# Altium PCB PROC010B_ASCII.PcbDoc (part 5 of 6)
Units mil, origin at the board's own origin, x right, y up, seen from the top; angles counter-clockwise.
Board outline 3180 x 2565 mil, 6 copper layers (TOP, L2, L3, L4, L5, BOTTOM), stack 55.54 mil thick; 362 components, 264 nets, 1248 pads, 1144 vias.
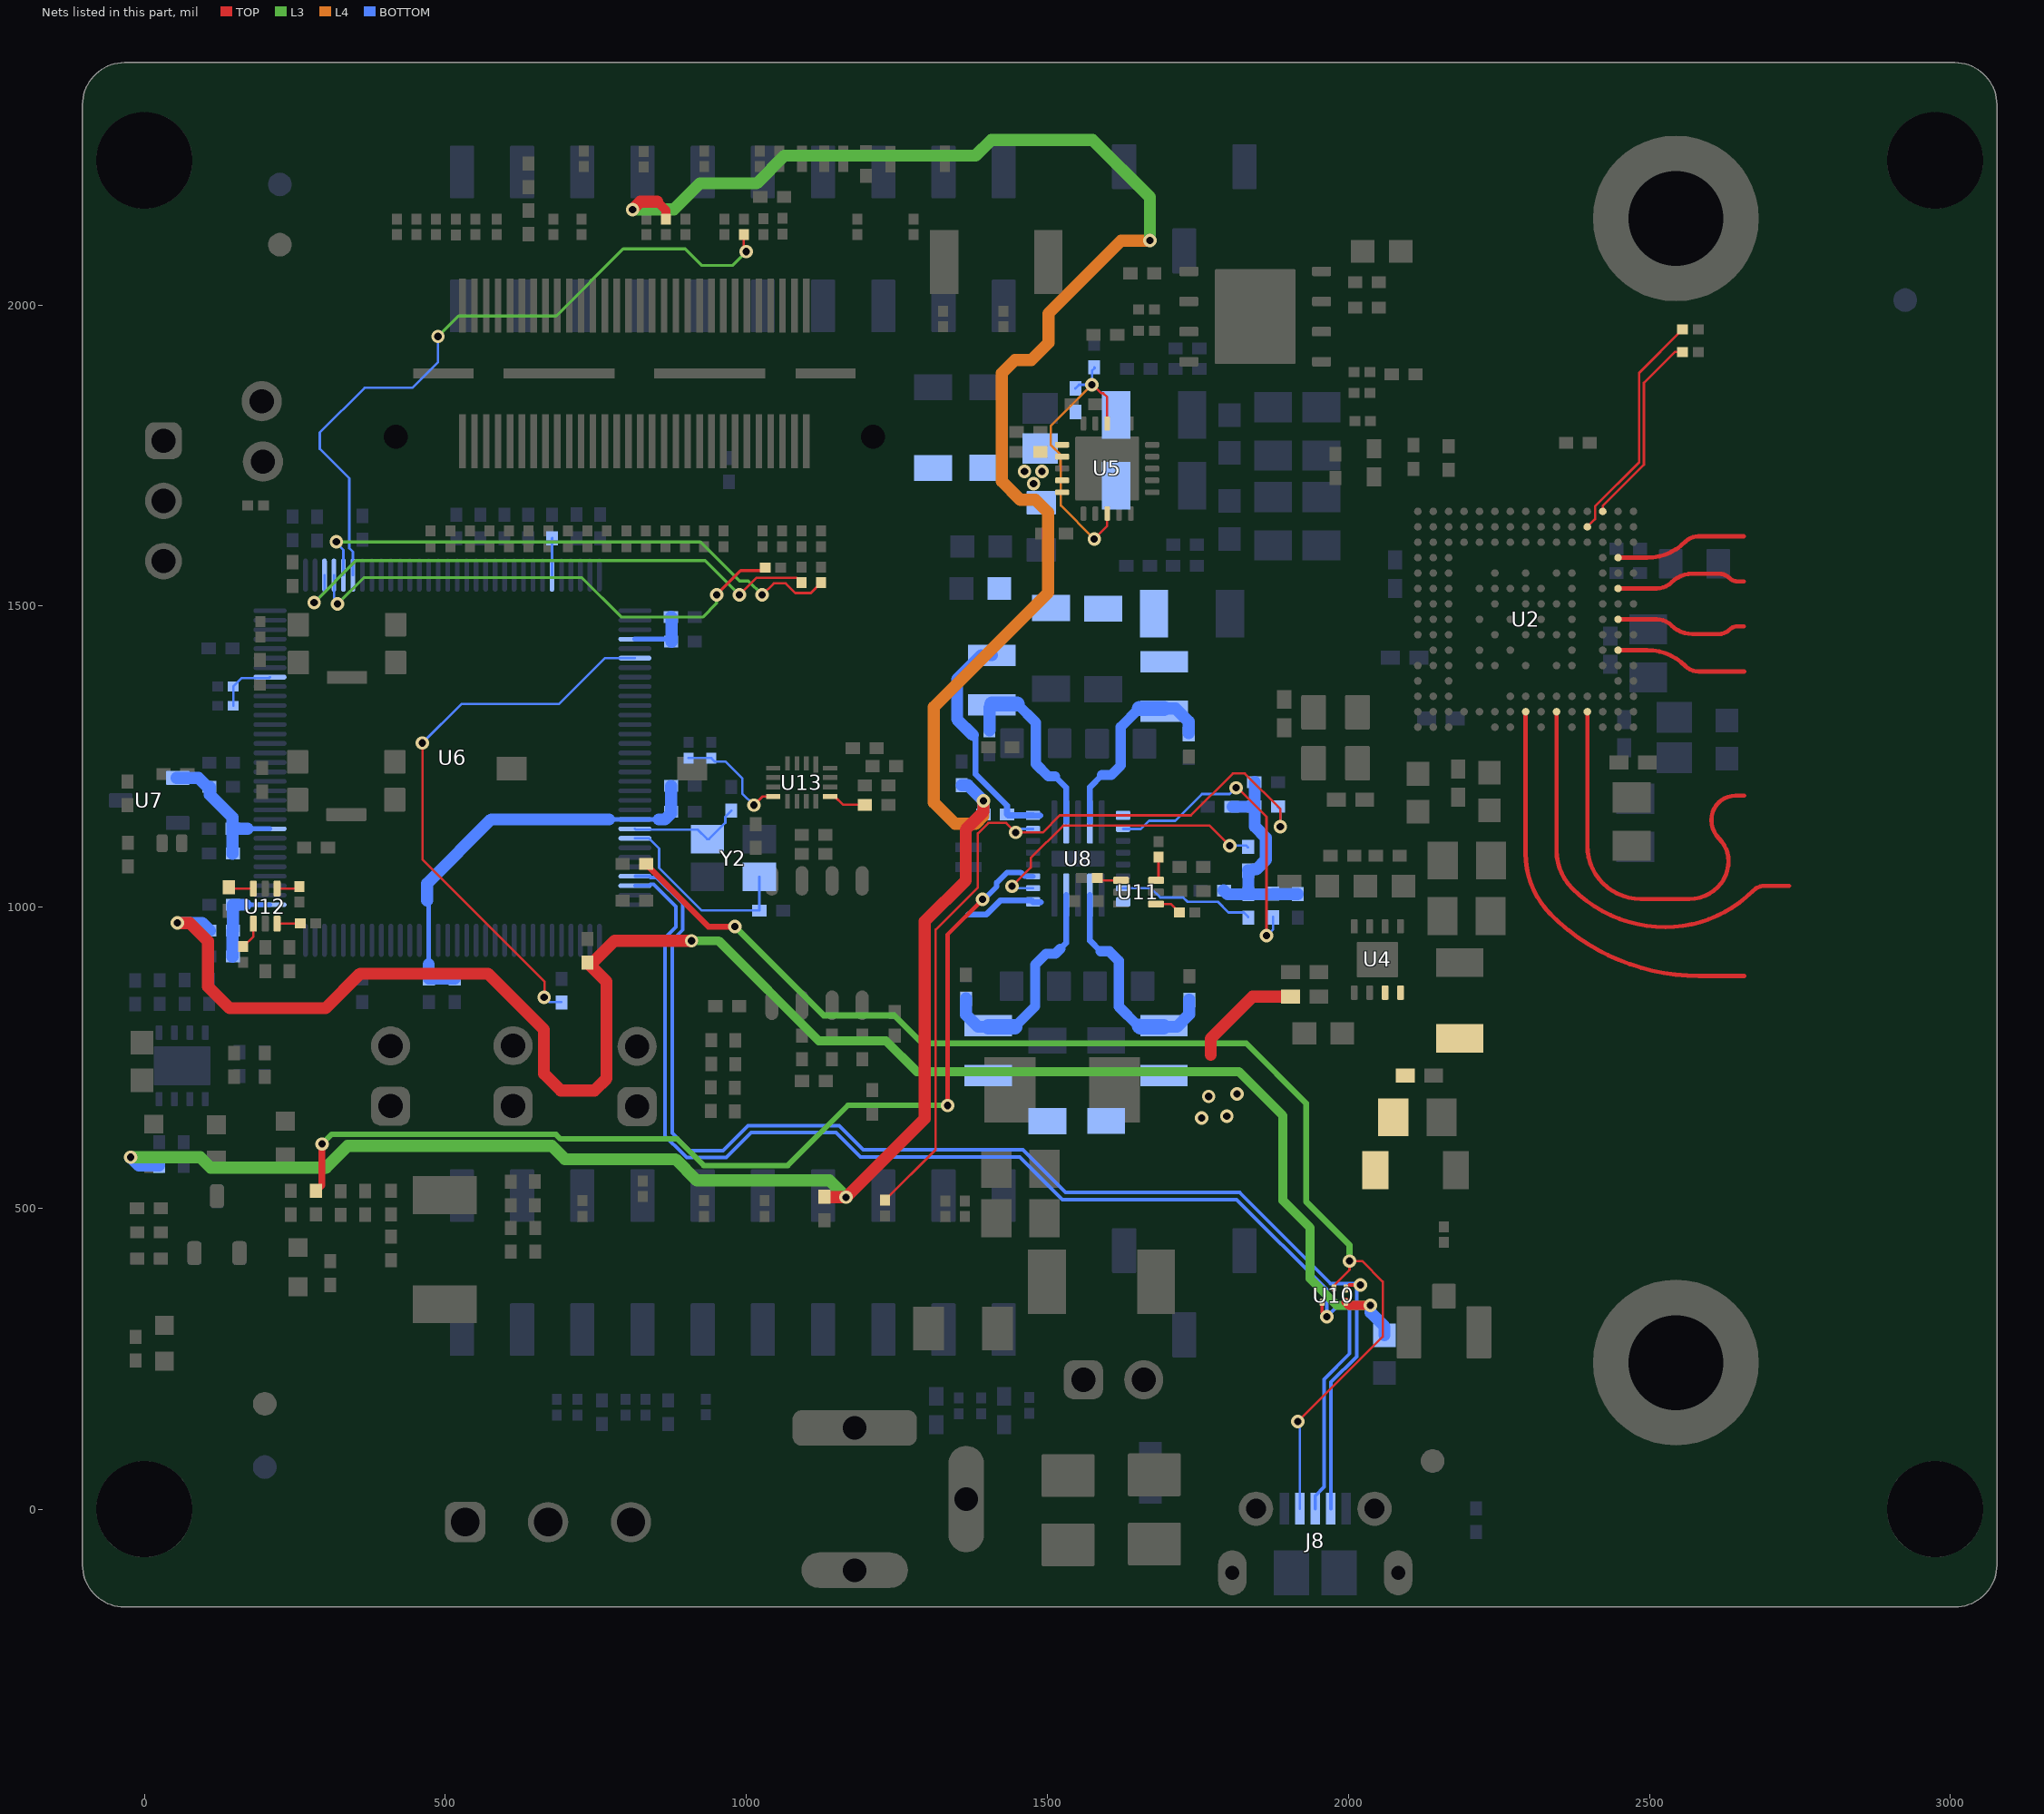
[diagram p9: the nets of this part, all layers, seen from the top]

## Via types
v1: diameter 22.4, hole 12.2, TOP to BOTTOM, tented both sides, 621 vias
v2: diameter 15.74, hole 5.9, TOP to L2, tented top, 508 vias
v3: diameter 19.68, hole 7.87, TOP to BOTTOM, tented top, 7 vias
v4: diameter 19.68, hole 7.87, TOP to BOTTOM, 4 vias
v5: diameter 19.68, hole 7.87, TOP to BOTTOM, tented both sides, 3 vias
v6: diameter 19.68, hole 7.87, TOP to BOTTOM, tented bottom, 1 vias

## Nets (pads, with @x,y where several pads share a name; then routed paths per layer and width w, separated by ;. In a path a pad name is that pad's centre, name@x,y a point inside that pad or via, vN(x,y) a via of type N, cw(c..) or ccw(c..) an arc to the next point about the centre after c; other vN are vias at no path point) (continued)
NetR180_2: R180.2 U11.1 | length 41.2
  TOP w4: R180.2@1582.77,1048.33 1586.66,1044.44 U11.1@1622.33,1044.44
NetR181_1: R181.1 U11.4 | length 44.4
  TOP w4: U11.4@1680.59,1005.07 1705.34,1005.06 R181.1@1719.23,991.17
NetR182_1: R182.1 U11.6 | length 40
  TOP w4: U11.6@1680.59,1044.44 1684.67,1048.52 R182.1@1684.67,1082.79
NetR184_1: R184.1 U12.3 | length 41.4
  TOP w4: R184.1@140.38,1032.25 141.96,1030.67 U12.3@181.13,1030.67
NetR185_2: R185.2 U12.1 | length 38.8
  TOP w4: U12.1@220.5,1030.67 254.29,1030.67 R185.2@257.83,1034.21
NetR186_1: R186.1 U12.6 | length 38.7
  TOP w4: U12.6@220.5,972.4 257.87,972.41 R186.1@258.79,973.33
NetR188_2: R188.2 U12.4 | length 45.4
  TOP w4: R188.2@163.83,934.21 181.12,951.5 U12.4@181.13,972.4
NetR194_2: R194.2 U6.59 | length 61.9
  BOTTOM w4: U6.59@677.14,1551.19 677.14,1612.57 R194.2@677.52,1612.95
NetR195_1: R195.1 U13.13 | length 63.2
  TOP w4: U13.13@1139.1,1183.59 1146.9,1183.59 1160.68,1169.81 R195.1@1196.58,1169.81
NetR197_2: R197.2 U2.P4 | length 393.5
  TOP w4: U2.P4@2396.91,1631.44 2409.75,1644.28 2409.75,1665.25 2483,1738.5 2483,1887.2 2555.01,1959.21 R197.2@2555.01,1959
NetR198_2: R198.2 U2.R3 | length 327.3
  TOP w4: U2.R3@2422.5,1657.03 2422.5,1666 2491,1734.5 2491,1870.64 2542.36,1922 R198.2@2555.01,1922
PGOOD: R27.1 R107.2 R138.2 R141.2 R159.1 | length 4589.2
  TOP w15: 852.15,2171.36 866.61,2156.9 R27.1@866.61,2142.71
  TOP w20: v1(811,2158.5) 823.86,2171.36 852.15,2171.36 ; R107.2@1129.75,518.18 v1(1165.78,518.18) 1296.38,648.78 1296.38,976.2 1364.54,1044.36 1364.54,1129.13 1393.72,1158.31 v1(1393.72,1176.67)
  L3 w20: v1(-23,584.5) 93.04,584.5 110.2,567.34 301.89,567.34 337.84,603.3 676.71,603.3 698.74,581.28 882.26,581.28 917.54,546 1137.96,546 v1(1165.78,518.18) ; v1(811,2158.5) 879.46,2158.5 922.83,2201.86 1017.13,2201.86 1063.27,2248 1381,2248 1407,2274 1575.14,2274 1670.34,2178.8 v1(1670.34,2106.77)
  L4 w20: v1(1393.72,1176.67) 1393.72,1150.96 1381.05,1138.3 1346.64,1138.3 1311.35,1173.59 1311.35,1332.35 1501.24,1522.24 1501.24,1655.5 1480.29,1676.45 1454.85,1676.45 1424.36,1706.93 1424.36,1886.63 1446.28,1908.55 1473.25,1908.55 1501.76,1937.06 1501.76,1985.85 1622.68,2106.77 v1(1670.34,2106.77)
  BOTTOM w20: v1(-23,584.5) -9.31,570.81 R159.1@24.43,570.81 ; R138.2@1357.78,1202.28 1368.11,1202.28 v1(1393.72,1176.67) R141.2@1393.72,1154.01
PMIC_1V0: C30.2 C31.2 C32.2 C40.2 C81.2 L4.2 L5.1 L8.1 R46.1 R120.2 U5.1 U5.2 U5.4 U5.5 U8.1 | length 130.9
  BOTTOM w10: 1368.72,987.88 1398.93,987.88 1422.37,1011.32 1473.53,1011.32 U8.1@1476.2,1008.65 ; U8.1@1476.2,1007.88 1488.82,1007.88
  other v1: 1477.07,1703.31 1461.98,1723.32 1491.25,1723.21
PMIC_1V2: C54.2 L1.2 L9.1 U8.14
PMIC_1V8: C21.1 C23.1 C25.1 C82.2 L3.2 L7.1 R84.2 U4.7 U4.8 U8.21 | length 188.3
  TOP w20: 1771.28,754.5 1771.28,781.5 1841,851.22 R84.2@1903.73,851.22
  other v1: 1756,649.5 1798,652.5 1768,685.5 1815,689.5
PMIC_CLK: R97.2 U8.3 | length 1666.1
  TOP w7.08: v1(1334.3,670.49) 1334.3,954.63 v1(1392.53,1012.86)
  TOP w11: R97.2@285,528.05 295,538.05 v1(295,606.5)
  L3 w9: v1(295,606.5) 310.78,622.28 683.9,622.28 691.42,614.75 885.25,614.75 929.05,570.95 1068.95,570.95 1168.49,670.49 v1(1334.3,670.49)
  BOTTOM w9: v1(1392.53,1012.86) 1394.86,1012.86 1416,1034 1416,1040.48 1433.11,1057.59 1455.85,1057.59 1462.47,1050.97 U8.3@1476.2,1050.97
PMIC_EN1: R102.2 R142.1 U8.7 | length 1350.2
  TOP w4: R102.2@1230.25,513.27 1314.37,597.39 1314.37,962.49 1384.59,1032.71 1384.59,1122.31 1401.99,1139.71 1431.79,1139.71 v1(1447.5,1124) 1492.41,1124 1520.75,1152.33 1738.33,1152.33 1808,1222 1828,1222 1887,1163 v1(1887,1133.5)
  BOTTOM w4: v1(1447.5,1124) 1453.21,1129.71 U8.7@1476.2,1129.71 ; R142.1@1882.25,1167.04 1887,1162.29 v1(1887,1133.5)
PMIC_EN2: R148.1 U8.15 | length 520.5
  TOP w4: v1(1813.65,1198) 1816,1198 1864,1150 v1(1864,952.5)
  BOTTOM w4: U8.15@1625.81,1129.71 1655.21,1129.71 1668.82,1143.32 1712.32,1143.32 1756.81,1187.81 1802.78,1187.81 1813.65,1198.69 v1(1813.65,1198) ; v1(1864,952.5) 1875,963.5 R148.1@1875,983.6
PMIC_EN3: R145.1 U8.2 | length 494.2
  TOP w4: v1(1441.5,1034.5) 1472.48,1065.48 1472.48,1081.57 1526.25,1135.33 1769.67,1135.33 v1(1803,1102)
  BOTTOM w4: v1(1441.5,1034.5) 1444.71,1031.29 U8.2@1476.2,1031.28 ; v1(1803,1102) 1830.49,1102 R145.1@1833.44,1099.05
PMIC_NRST: R150.2 U8.20 | length 227.8
  BOTTOM w4: U8.20@1625.81,1031.28 1672.21,1031.29 1687.5,1016 1725.5,1016 1732.5,1009 1782.99,1009 1800.99,991 1825.99,991 R150.2@1833.74,983.25
PMICOUT_3V3: C55.2 L2.2 R133.1 R141.1 U8.8 | length 388.9
  BOTTOM w10: 1376.47,1285.53 1380.65,1281.35 1380.65,1220.85 1433.09,1168.41 R141.1@1433.09,1154.01 1434.74,1152.35 U8.8@1476.2,1152.35 ; U8.8@1476.2,1152.15 1488.2,1152.15
  BOTTOM w20: 1376.47,1285.53 1350,1312 1350,1378.33 1389.91,1418.24 L2.2@1407.85,1418.24
PMICVIO_3V3: R139.2 R142.2 R143.2 R145.2 R147.2 R148.2 R149.1 R150.1 | length 376.5
  BOTTOM w20: R147.2@1792.9,1027.5 1799.35,1021.05 R150.1@1833.74,1021.05 ; R143.2@1807.91,1166.5 R142.2@1844.45,1167.04 ; R139.2@1844.45,1207.54 R142.2@1844.45,1167.04 ; R149.1@1916.14,1021.05 1915.79,1021.4 1875,1021.4 1874.65,1021.05 R150.1@1833.74,1021.05 ; R150.1@1833.74,1021.05 1833.74,1060.95 1833.44,1061.25 1840.75,1061.25 1842,1062.5 1847,1062.5 1863,1078.5 1863,1115 1844.45,1133.55 R142.2@1844.45,1167.04
RX1: U2.M2 | length 218.6
  TOP w7.08: U2.M2@2448.09,1580.26 2496.4,1580.26 ccw(c2496.4,1669.28) 2559.79,1606.78 cw(c2581.07,1585.5) 2581.07,1615.6 2657.22,1615.6
RX2: U2.K2 | length 218.8
  TOP w7.08: U2.K2@2448.09,1529.08 2512.28,1529.08 ccw(c2512.28,1563.6) 2536.69,1539.19 cw(c2571.24,1504.66) 2571.24,1553.5 2615.82,1553.5 cw(c2615.82,1528.95) 2633.18,1546.31 ccw(c2646.47,1559.58) 2646.47,1540.8 2656.92,1540.8
RX3: U2.H2 | length 218.8
  TOP w7.08: U2.H2@2448.09,1477.9 2512.28,1477.9 cw(c2512.28,1443.38) 2536.69,1467.79 ccw(c2571.24,1502.32) 2571.24,1453.48 2615.82,1453.48 ccw(c2615.82,1478.03) 2633.18,1460.67 ; 2633.19,1460.68 cw(c2646.47,1447.4) 2646.47,1466.18 2656.92,1466.18
RX4: U2.F2 | length 218.9
  TOP w7.08: U2.F2@2448.09,1426.72 2496.4,1426.72 cw(c2496.4,1337.7) 2559.79,1400.2 ccw(c2581.5,1421.91) 2581.5,1391.2 2657.4,1391.2
SPICLK1: R75.1 R76.1 U13.8 | length 193.5
  TOP w4: v1(1012.58,1169.33) 1026.83,1183.59 U13.8@1044.61,1183.59
  BOTTOM w4: R75.1@904.07,1247.48 R76.1@941.93,1247.48 947.94,1241.48 965.54,1241.48 993.15,1213.86 993.15,1188.75 v1(1012.58,1169.33)
SS_CTRL: R119.2 R120.1 U5.8 U5.18 | length 504.4
  TOP w4: v1(1574.07,1867.4) 1575.74,1867.4 1589.91,1853.24 1592.9,1853.24 1599.35,1846.8 U5.18@1599.35,1803.12 ; v1(1577.96,1611.47) 1599.35,1632.86 U5.8@1599.35,1653.52
  L4 w4: v1(1574.07,1867.4) 1505.5,1798.83 1505.5,1767.57 1521.82,1751.25 1521.82,1731.91 1522.36,1731.91 1522.36,1667.08 v1(1577.96,1611.47)
  BOTTOM w4: R120.1@1546.63,1861.48 1552.56,1867.4 v1(1574.07,1867.4) 1574.07,1890.75 1578.87,1895.55 R119.2@1577.96,1896.45
SW0: L2.1 R190.2 U8.10 | length 322.3
  BOTTOM w10: 1512.51,1217 1531.31,1198.2 U8.10@1531.32,1141.13
  BOTTOM w17: 1449.82,1337.53 1480.85,1306.5 1480.85,1237.8 1501.65,1217 1512.51,1217
  BOTTOM w20: R190.2@1403.85,1293.43 1403.85,1331.56 L2.1@1407.85,1335.56
  BOTTOM w25: L2.1@1407.85,1337.53 1449.82,1337.53
SW1: L1.1 R191.2 U8.12 | length 342.4
  BOTTOM w10: U8.12@1570.69,1141.13 1570.69,1199.24 1590.95,1219.5
  BOTTOM w17: 1590.95,1219.5 1606.05,1219.5 1621.95,1235.4 1621.95,1299.23 1652.68,1329.96
  BOTTOM w20: L1.1@1694.05,1329.96 1713.07,1329.96 1734.8,1308.23 R191.2@1734.8,1288.55
  BOTTOM w25: 1652.68,1329.96 L1.1@1694.05,1329.96
SW2: L4.1 R192.2 U8.25 | length 379.6
  BOTTOM w10: 1521.55,930.8 1531.31,940.56 U8.25@1531.32,1019.87
  BOTTOM w17: 1445.92,801.17 1479.85,835.1 1479.85,904.34 1498.01,922.5 1513.25,922.5 1521.55,930.8
  BOTTOM w20: R192.2@1364.9,848.45 1364.9,821.17 1384.9,801.17 L4.1@1401.55,801.17
  BOTTOM w25: L4.1@1401.55,801.17 1445.92,801.17
SW3: L3.1 R193.2 U8.23 | length 377.5
  BOTTOM w10: U8.23@1570.69,1019.87 1570.69,944.32 1588.51,926.5
  BOTTOM w17: 1588.51,926.5 1602.85,926.5 1618.65,910.7 1618.65,834.7 1650.84,802.51 1652.68,802.51
  BOTTOM w20: L3.1@1693.55,801.17 1714.99,801.17 1735.6,821.78 R193.2@1735.6,846.45
  BOTTOM w25: 1652.68,802.51 1654.02,801.17 L3.1@1693.55,801.17
TX1: U2.B4 | length 696.2
  TOP w7.08: U2.B4@2396.91,1324.36 2396.91,1102.05 ccw(c2485.46,1102.05) 2485.46,1013.5 2566.65,1013.5 ccw(c2566.65,1079.79) 2613.53,1032.92 ; 2613.54,1032.93 ccw(c2570.24,1076.22) 2631.47,1076.22 ccw(c2578.8,1076.22) 2616.05,1113.46 cw(c2647.37,1144.78) 2603.07,1144.78 cw(c2643.55,1144.8) 2614.93,1173.43 cw(c2642.62,1145.76) 2642.61,1184.9 2657.3,1184.9
TX2: U2.B6 | length 696.2
  TOP w7.08: U2.B6@2345.73,1324.36 2345.73,1094.33 ccw(c2435.71,1094.33) 2372.08,1030.71 ccw(c2526.5,1185.06) 2526.5,966.73 ccw(c2526.5,1172.53) 2672,1026.99 cw(c2692.07,1006.94) 2692.06,1035.3 2732.11,1035.3
TX3: U2.B8 | length 696.3
  TOP w7.08: U2.B8@2294.55,1324.36 2294.34,1324.15 2294.34,1089.06 ccw(c2437.96,1089.06) 2336.4,987.51 ccw(c2582.22,1233.3) 2582.22,885.68 2657.3,885.68
VBUS_1_DETECT: C69.2 R151.1 R153.2 U6.1 | length 147.8
  BOTTOM w8: 168.55,1003.95 U6.1@208.64,1003.95
  BOTTOM w20: R153.2@146.55,917.74 146.55,961.04 146.95,961.44 146.95,1003.56 147.34,1003.95 168.55,1003.95
VDDC_1: C62.2 C64.2 C74.2 C75.2 U6.87 U6.115 | length 701
  BOTTOM w8: 469.65,1010.85 472.42,1008.08 472.42,905.08 ; 771.82,1145.68 854.18,1145.68
  BOTTOM w20: 469.65,1010.85 469.65,1039.15 576.18,1145.68 771.82,1145.68 ; 472.42,905.08 472.42,881.71 472.68,881.45 C74.2@515.6,881.45 ; 854.18,1145.68 865,1145.68 874.96,1155.64 C64.2@874.96,1158.3 C62.2@874.96,1201.2
XDSET_1_D_N: J8.2 U6.93 U10.1 | length 2188.8
  TOP w6: U10.1@1995.68,366.33 2001.88,372.52 v1(2019.99,372.52)
  BOTTOM w6: U6.93@815.54,1051.19 838.99,1051.19 840.8,1049.38 850.87,1049.38 894.6,1005.65 894.6,962.25 876.6,944.24 876.6,624.75 905.6,595.75 905.6,595.5 961.6,595.5 1003.1,637 1153.9,637 1194.2,596.7 1459.1,596.7 1529.89,525.91 1819.18,525.91 1970.6,374.5 2019.6,374.5 2020.6,373.5 2013.6,366.5 2013.6,335.81 2013.6,253.5 1971.19,211.09 1971.19,32.06 J8.2@1971.19,0.88
XDSET_1_D_P: J8.3 U6.94 U10.4 | length 2188.5
  TOP w6: U10.4@1956.31,343.69 1956.31,327.19 v1(1964,319.5)
  BOTTOM w6: U6.94@814.94,1035.44 838.69,1035.44 841.03,1037.78 846.07,1037.78 883,1000.85 883,967.05 865,949.05 865,619.94 894,590.94 894,590.7 900.79,583.9 966.4,583.9 1007.9,625.4 1149.1,625.4 1189.4,585.1 1454.3,585.1 1525.09,514.31 1814.38,514.31 1964,364.69 v1(1964,319.5) 1984.5,340 1993,340 2002,331 2002,258.31 1959.59,215.9 1959.59,36.86 1945,22.27 J8.3@1945,0.88
XDSET_1_ID: J8.4 R152.2 U10.2 | length 2115.1
  TOP w4: v1(1916,145.5) 2057.04,286.54 2057.04,377.81 2022.74,412.11 v1(2001.89,412.11) 2001.89,397.39 1976,371.5 U10.2@1976,367.31
  TOP w10: R152.2@832.9,1071.5 936.9,967.5 v1(981,967.5)
  L3 w10: v1(981,967.5) 1128.41,820.09 1245.8,820.09 1292.12,773.77 1830.37,773.77 1929.79,674.35 1929.79,510.85 2001.89,438.76 v1(2001.89,412.11)
  BOTTOM w4: v1(1916,145.5) 1919.41,142.09 J8.4@1919.41,0.88
XDSET_1_VBUS: R151.2 R154.2 R161.2 U10.6 | length 3036.4
  TOP w15: U10.6@1995.68,343.69 2000.79,338.59 v1(2036.61,338.59)
  TOP w20: v1(55,973.5) 75.54,973.5 105.77,943.27 105.77,867.8 141.57,832 301,832 358.51,889.51 570.49,889.51 663.79,796.21 663.79,722.96 691.59,695.16 747.69,695.16 767.67,715.14 767.67,876.15 R154.2@736,907.81 744.88,907.81 781.07,944 v1(909,944)
  L3 w15: v1(909,944) 954.04,944 1120.15,777.89 1231.87,777.89 1282.88,726.87 1818.03,726.87 1891.09,653.81 1891.09,512.9 1936.34,467.65 1936.34,383.2 1980.95,338.59 v1(2036.61,338.59)
  BOTTOM w20: v1(55,973.5) 96.29,973.5 R151.2@108.75,961.04 ; v1(2036.61,338.59) 2036.61,326.66 2060,303.26 R161.2@2060,289
XDSET_LOGGER: R135.2 R136.2 U6.25 | length 99.3
  BOTTOM w4: R136.2@147.77,1334.29 R135.2@147.77,1366.19 162.08,1380.5 207.24,1380.5 U6.25@208.64,1381.9
XDSET_NRST: R155.1 U6.70 | length 951
  TOP w4: v1(462,1272.5) 462,1079.01 665,876.01 665,850 v1(664,850)
  BOTTOM w4: v1(462,1272.5) 527,1337.5 689.05,1337.5 765.05,1413.5 814.83,1413.5 U6.70@814.94,1413.39 ; v1(664,850) 665,850 672.75,842.25 R155.1@692.78,842.25
XDSET_OSC0: C70.2 U6.88 Y2.1 | length 192.6
  BOTTOM w4: U6.88@814.94,1129.93 816.37,1128.5 919.49,1128.5 Y2.1@935,1112.99 937.99,1112.99 965,1140 965,1150.16 C70.2@975,1160.16
XDSET_OSC1: C63.2 U6.89 Y2.3 | length 330.9
  BOTTOM w4: U6.89@814.94,1114.18 838.17,1114.18 855,1097.35 855,1065 925.64,994.36 C63.2@1021.61,994.36 Y2.3@1021.61,1050
XDSET_TCK: R70.2 U6.35 | length 929.6
  TOP w4: v1(988.42,1518.55) 1016.78,1546.91 1083.15,1546.91 R70.2@1091.33,1538.73
  L3 w5: v1(282,1505.5) 351.71,1575.21 931.76,1575.21 v1(988.42,1518.55)
  BOTTOM w4: v1(282,1505.5) 299.19,1522.69 U6.35@299.19,1551.19
XDSET_TDI: R30.2 U6.38 | length 1170.3
  TOP w4: R30.2@995.75,2116.73 995.75,2093.75 1000,2089.5 v1(1000,2088.5)
  L3 w5: v1(487.75,1947.66) 521.88,1981.78 684.05,1981.78 795.46,2093.2 898.29,2093.2 926.04,2065.45 976.95,2065.45 v1(1000,2088.5)
  BOTTOM w4: U6.38@346.44,1551.19 346.44,1590.07 340.54,1595.97 340.54,1711.96 291.56,1760.94 291.56,1788.05 365.97,1862.46 444.96,1862.46 487.75,1905.25 v1(487.75,1947.66)
XDSET_TDO: R71.2 U6.37 | length 923.6
  TOP w4: v1(1026.32,1518.55) 1045.4,1537.64 1065.2,1537.64 1081.32,1521.51 1107.12,1521.51 R71.2@1124.33,1538.73
  L3 w5: v1(319,1606.5) 923.66,1606.5 988.55,1541.61 1003.26,1541.61 v1(1026.32,1518.55)
  BOTTOM w4: v1(319,1606.5) 319,1604.5 330.69,1592.81 U6.37@330.69,1551.19
XDSET_TMS: R69.2 U6.36 | length 847.8
  TOP w5: v1(950.52,1518.55) 990.59,1558.62 1026.11,1558.62 R69.2@1031.11,1563.62
  L3 w5: v1(321,1503.5) 364.66,1547.16 726.88,1547.16 792.54,1481.5 927.47,1481.5 950.52,1504.55 v1(950.52,1518.55)
  BOTTOM w4: U6.36@314.94,1551.19 314.94,1509.56 v1(321,1503.5)
XDSET_VBAT: C49.2 R134.1 U6.68 | length 104.2
  BOTTOM w8: U6.68@814.94,1444.89 871.46,1444.89 R134.1@875.75,1440.6
  BOTTOM w20: C49.2@875.05,1481.9 875.75,1481.2 R134.1@875.75,1440.6
XDSET_VREFA: C66.2 C67.2 R140.1 U6.9 U7.1 | length 250.2
  BOTTOM w8: 171.57,1129.93 U6.9@208.64,1129.93
  BOTTOM w20: U7.1@53.36,1214.49 89.72,1214.49 104.69,1199.52 108.75,1199.52 108.75,1186.75 146.49,1149.01 C66.2@146.49,1130.1 ; C67.2@146.55,1088.8 146.49,1088.86 C66.2@146.49,1130.1 ; 171.57,1129.93 146.66,1129.93 C66.2@146.49,1130.1
pads on no net: FID1.1 FID2.1 FID3.1 FID4.1 FID5.1 FID6.1 FID7.1 J1.15 J1.17 J1.19 J1.21 J1.23 J1.25 J1.27 J1.29 J1.31 J1.33 J1.35 J1.37 J1.39 J1.41 J1.43 J1.45 J1.47 J1.49 J1.MH1 J1.MH2 J5.3 J5.11 J6.4 J6.7 J6.20 J8.7 J8.8 LBL1.0 SW1.1 SW1.3 SW2.1 SW2.3 U1. U2.B15 U2.D1 U5.9 U5.17 U5.21@1571.99,1700.96 U5.21@1571.99,1755.68 U5.21@1626.71,1700.96 U5.21@1626.71,1755.68 U6.2 U6.3 U6.4 U6.5 U6.6 U6.11 U6.12 U6.13 U6.14 U6.15 U6.18 U6.19 U6.20 U6.21 U6.22 U6.23 U6.24 U6.27 U6.29 U6.30 U6.31 U6.32 U6.41 U6.42 U6.43 U6.44 U6.45 U6.46 U6.49 U6.50 U6.53 U6.54 U6.56 U6.57 U6.65 U6.67 U6.71 U6.72 U6.73 U6.74 U6.75 U6.76 U6.77 U6.78 U6.81 U6.82 U6.83 U6.84 U6.85 U6.86 U6.91 U6.92 U6.97 U6.98 U6.99 U6.100 U6.102 U6.103 U6.104 U6.105 U6.106 U6.107 U6.108 U6.109 U6.110 U6.111 U6.112 U6.116 U6.117 U6.118 U6.119 U6.120 U6.121 U6.123 U6.124 U6.125 U6.126 U6.127 U6.128 U7.3 U8. U9.7 U9.9@38.03,736.32 U9.9@87.64,736.32 U13.9 U13.12

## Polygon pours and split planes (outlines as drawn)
no net on Top Solder (solid, pour order 1226): 1710.23,1993.88 1762.33,1993.88 1762.33,2017.48 1710.23,2017.48 1710.23,1993.88
no net on Top Solder (solid, pour order 1228): 1710.23,2043.88 1762.33,2043.88 1762.33,2067.48 1710.23,2067.48 1710.23,2043.88
no net on Top Solder "Top Solder-No Net" (solid, pour order 1234): 69 vertices, not listed, extent 2260,825.7 3047,1773.5
no net on Top Solder (solid, pour order 1233): 1596,2324.5 1596,2219.5 1974,2219.5 1974,2146.5 2358,2146.5 2358,2324.5 1596,2324.5
no net on Bottom Solder "Bottom Solder-No Net" (solid, pour order 1235): 3068.95,-131.45 2330.5,-131.45 2330.48,-131.48 2318.95,-131.48 2318.95,618.55 3068.95,618.55 3068.95,-131.45
no net on Bottom Solder (solid): 43 vertices, not listed, extent 1991,-132.5 3047,2365
AR_1P3_RF2 on TOP "GND 1-No Net" (solid, remove dead copper, pour order 1254): 1657.89,1682.73 1657.89,1713.42 1663.59,1719.12 1690.73,1719.12 1695.53,1714.32 1695.53,1678.14 1689.72,1672.34 1668.28,1672.34
AR_1P3_RF1 on TOP "GND 1-No Net" (solid, remove dead copper, pour order 1252): 1785.39,1652.08 1833.48,1700.17 1833.48,1791.4 1790.17,1834.71 1716.34,1834.71 1658.82,1777.19 1658.82,1744.08 1664.23,1738.67 1689.96,1738.67 1706.01,1722.61 1706.01,1632.47 1727,1611.48 1744.79,1611.48
PMIC_1V0 on TOP "GND 1-No Net" (solid, remove dead copper, pour order 1250): 1450.36,1705.57 1479.75,1676.17 1534.9,1676.18 1542.33,1683.6 1542.33,1768.21 1535.03,1775.51 1478.9,1775.51 1450.36,1746.97
GND on TOP "TOP-GND 1" (solid, remove dead copper, pour order 1179): 2395.5,94 2694.5,94 2694.5,396 2395.5,396 2395.5,94
GND on TOP "TOP-GND 12" (solid, remove dead copper, pour order 1172): 32 vertices, not listed, extent 1348,789 1754,923
GND on TOP "TOP-GND 11" (solid, remove dead copper, pour order 1170): 18 vertices, not listed, extent 1429,1204 1749.46,1305.1
GND on TOP "TOP-GND 10" (solid, remove dead copper, pour order 1145): 1644.54,995.52 1644.54,1019.98 1622,1019.98 1622,1029.52 1644.54,1029.52 1644.54,1057 1658.38,1057 1658.38,1039.67 1658.37,1039.67 1658.37,995.52 1644.54,995.52
GND on TOP "TOP-GND 7" (solid, remove dead copper, pour order 1180): 1414,86.5 1414,48.5 1486,-23.5 1724,-23.5 1726,-25.5 1726,-89.5 1692,-123.5 1116,-123.5 1091,-98.5 1091,14.5 1108,31.5 1270,31.5 1347.48,108.98 1391.52,108.98
GND on TOP "TOP-GND 4" (solid, remove dead copper, pour order 1162): 34 vertices, not listed, extent 2653.04,1286.86 2946.35,1345.92
GND on TOP "TOP-GND 3" (solid, remove dead copper, pour order 1163): 34 vertices, not listed, extent 2653.04,1660.87 2946.35,1719.93
RX1 on TOP "TOP-RX1" (solid, remove dead copper, pour order 1161): 34 vertices, not listed, extent 2653.04,1586.07 2946.35,1645.13
RX2 on TOP "TOP-RX2" (solid, remove dead copper, pour order 1155): 34 vertices, not listed, extent 2653.04,1511.27 2946.35,1570.32
RX3 on TOP "TOP-RX3" (solid, remove dead copper, pour order 1158): 34 vertices, not listed, extent 2653.04,1436.47 2946.35,1495.52
RX4 on TOP "TOP-RX4" (solid, remove dead copper, pour order 1159): 34 vertices, not listed, extent 2653.04,1361.66 2946.35,1420.72
TX1 on TOP "TOP-TX1" (solid, remove dead copper, pour order 1160): 34 vertices, not listed, extent 2653.04,1155.37 2946.35,1214.43
TX2 on TOP "TOP-TX2" (solid, remove dead copper, pour order 1156): 34 vertices, not listed, extent 2727.85,1005.77 3021.15,1064.82
TX3 on TOP "TOP-TX3" (solid, remove dead copper, pour order 1157): 34 vertices, not listed, extent 2653.04,856.16 2946.35,915.21
5V_IN on TOP "TOP-5V_IN 2" (solid, remove dead copper, pour order 1173): 1465,231 1465,600.33 1533.41,600.33 1533.41,352.09 1580,305.5 1603,282.5 1603,173.5 1602.5,173 1523,173
5V_IN on TOP "TOP-5V_IN 1" (solid, remove dead copper, pour order 1174): 409,328.5 438,357.5 647,357.5 667,337.5 667,187.5 653,173.5 430,173.5 409,194.5 409,328.5
5V_IN on TOP "TOP-5V_IN" (solid, remove dead copper, pour order 1169): 1617,2184 1598.5,2202.5 1512.78,2202.5 1469.96,2159.68 1469.96,2025.46 1486.92,2008.5 1545.11,2008.5 1617,2080.38
AR_1V8 on TOP "TOP-AR_1V8" (solid, remove dead copper, pour order 1168): 22 vertices, not listed, extent 2054,880 2230,1123
AR_VOUT_PA on TOP "TOP-AR_VOUT_PA" (solid, remove dead copper, pour order 1164): 17 vertices, not listed, extent 2434,1152.5 2546,1331.48
NetJ1_1 on TOP "TOP-UNNAMED_6_QSH03001XD_I1_1" (solid, remove dead copper, pour order 1175): 29 vertices, not listed, extent 1074.64,1728.5 1352,2133.5
MCU_5V on TOP "TOP-MCU_5V" (solid, remove dead copper, pour order 1166): 444,535.5 417,562.5 417,594.5 432,609.5 576,609.5 588,597.5 588,569.5 553,534.5 553,506.5 552,505.5 445,505.5 444,506.5 444,535.5
GND on TOP "GND 1-No Net" (solid, remove dead copper, pour order 1154): 1222.3,1210.76 1222.3,1158.69 1223.78,1157.21 1256.62,1157.21 1272.75,1173.35 1272.75,1211.41 1266.28,1217.88 1229.42,1217.88
5V_UNREG on TOP "TOP-5V_UNREG" (solid, remove dead copper, pour order 1171): 1645.66,428.88 1666.78,450 1760,450 1765,445 1765,177 1627,177 1627,282 1645.66,300.66
NetC26_1 on TOP "TOP-UNNAMED_9_CAPPOLARIZED_I74_1" (solid, remove dead copper, pour order 1178): 36 vertices, not listed, extent 1368.3,20.3 1735.5,757
GND on TOP "TOP-GND 6" (solid, remove dead copper, pour order 1167): 1673.76,615.01 1695,636.25 1695,676 1694.5,676.5 1694.5,735.5 1670,760 1576.63,760 1555.01,738.38 1555.01,642.99 1582.99,615.01
AR_1V2 on TOP "GND 1-No Net" (solid, remove dead copper, pour order 1165): 2344.78,1819.06 2370.22,1819.06 2379.16,1810.12 2379.16,1703.66 2355.11,1679.62 2355.11,1648.99 2351.76,1645.64 2341.19,1645.64 2337.64,1649.19 2337.64,1664.71 2318.55,1683.8 2318.55,1792.83
GND on TOP "TOP-GND" (solid, remove dead copper, pour order 1181): 2358,2324.5 2358,2146.5 1974,2146.5 1974,2219.5 1596,2219.5 1596,2324.5 2358,2324.5
NetF1_2 on TOP "TOP-UNNAMED_9_FUSE_I161_1" (solid, remove dead copper, pour order 1176): 92 vertices, not listed, extent 1062.23,96.19 1335.51,337.5
AR_1V2 on TOP "GND 1-No Net" (solid, remove dead copper, pour order 1244): 2043.97,1686.48 1972.44,1686.48 1963.98,1694.94 1963.98,1729.6 1971.63,1737.26 2053.7,1737.26 2058.49,1732.46 2058.49,1701.01
PMIC_1V8 on TOP "TOP-PMIC_2V3" (solid, remove dead copper, pour order 1177): 2224.8,870.55 2242.73,852.62 2242.73,763.68 2234.05,755 2129.43,755 2111.4,736.97 2111.4,522.48 2095.52,506.59 1742,506.59 1742,760.5 2019.66,760.5 2048.41,789.24 2048.41,860.76 2058.2,870.55
GND on TOP "TOP-GND 8" (solid, remove dead copper, pour order 1182): 996 vertices, not listed, extent 2124.85,-132.5 3047,1773.7
AR_1V2 on BOTTOM "GND 1-No Net" (solid, remove dead copper, pour order 1256): 1746.43,1467.51 1767.36,1446.57 1829.15,1446.57 1835.75,1453.17 1835.75,1529.07 1802.53,1562.29 1770.65,1562.29 1752.19,1543.57 1746.43,1537.8
GND on BOTTOM "BOTTOM-GND 8" (solid, remove dead copper, pour order 1224): 352 vertices, not listed, extent 1776.02,-130 3047.25,2366
AR_1P3_RF2 on BOTTOM "BOTTOM-AR_1P3_RF2" (solid, remove dead copper, pour order 1222): 47 vertices, not listed, extent 1708.12,1288.88 2802.34,1984.69
PMIC_1V2 on BOTTOM "GND 1-No Net" (solid, remove dead copper, pour order 1215): 25 vertices, not listed, extent 1553.42,1137.52 1856.66,1527.27
GND on BOTTOM "BOTTOM-GND 2" (solid, remove dead copper, pour order 1206): 1274.3,1801.29 1518.28,1801.29 1520.83,1803.84 1520.83,1861.25 1489.51,1892.57 1452.93,1892.57 1438.72,1906.78 1276.57,1906.78 1262,1892.22 1262,1813.59
5V_UNREG on BOTTOM "BOTTOM-5V_UNREG 3" (solid, remove dead copper, pour order 1201): 17 vertices, not listed, extent 1422,1105 1516.55,1312.76
GND on BOTTOM "BOTTOM-GND 6" (solid, remove dead copper, pour order 1212): 75 vertices, not listed, extent 1466.05,1105 1634.15,1383.5
GND on BOTTOM "BOTTOM-GND 5" (solid, remove dead copper, pour order 1211): 38 vertices, not listed, extent 1464.95,756.8 1631.55,1055.8
GND on BOTTOM "BOTTOM-GND 4" (solid, remove dead copper, pour order 1213): 1784.53,1796.5 1783.56,1797.48 1783.55,1847.73 1779.06,1852.22 1779.06,1910.56 1795,1926.5 1984,1926.5 2000,1910.5 2000,1810.73 1985.77,1796.5
GND on BOTTOM "BOTTOM-GND 3" (solid, remove dead copper, pour order 1202): 17 vertices, not listed, extent 2401,1353.52 2588,1416.5
5V_UNREG on BOTTOM "BOTTOM-5V_UNREG 1" (solid, remove dead copper, pour order 1205): 18 vertices, not listed, extent 1584.05,839.8 1711.12,1056
PMICOUT_3V3 on BOTTOM "BOTTOM-PMICOUT_3V3" (solid, remove dead copper, pour order 1209): 1462.22,1549 1520.6,1549 1540,1529.6 1540,1456.5 1484.04,1400.54 1368.25,1400.54 1368.25,1469.25 1396.57,1497.57 1396.57,1549
AR_1V8 on BOTTOM "BOTTOM-AR_1V8" (solid, remove dead copper, pour order 1198): 2424,1430.5 2424,1465.5 2434.98,1476.48 2526.78,1476.48 2527,1476.27 2527,1433.5 2453,1433.5 2450,1430.5 2424,1430.5
AR_VOUT_PA on BOTTOM "BOTTOM-AR_VOUT_PA" (solid, remove dead copper, pour order 1207): 2609,1264.5 2653,1264.5 2653,1185.5 2620,1152.5 2441,1152.5 2437,1156.5 2437,1200.5 2443,1206.5 2589,1206.5 2609,1226.5 2609,1264.5
MCU_5V on BOTTOM "BOTTOM-MCU_5V 1" (solid, remove dead copper, pour order 1208): 1783,347.5 1766,364.5 1766,475.5 1779,488.5 1824.86,488.5 1891,422.36 1891,356.5 1882,347.5 1783,347.5
MCU_5V on BOTTOM "BOTTOM-MCU_5V" (solid, remove dead copper, pour order 1210): 17 vertices, not listed, extent 415,464 584,597
5V_UNREG on BOTTOM "BOTTOM-5V_UNREG 2" (solid, remove dead copper, pour order 1203): 17 vertices, not listed, extent 1585,1105 1710.68,1313.16
PMIC_1V8 on BOTTOM "BOTTOM-PMIC_2V3 1" (solid, remove dead copper, pour order 1217): 18 vertices, not listed, extent 1560,593.4 1854.85,1029.4
5V_UNREG on BOTTOM "BOTTOM-5V_UNREG" (solid, remove dead copper, pour order 1204): 33 vertices, not listed, extent 1390.05,839.8 1518,1055.8
GND on BOTTOM "BOTTOM-GND 7" (solid, remove dead copper, pour order 1219): 375 vertices, not listed, extent 1574,144.5 1990.98,579
GND on BOTTOM "BOTTOM-GND" (solid, remove dead copper, pour order 1223): 2866.5,-131.45 2330.5,-131.45 2330.48,-131.48 2318.95,-131.48 2318.95,618.55 3047,618.55 3047,136 2916,136 2878,98 2871,91 2871,-131.45 2866.5,-131.45
AR_1V8 on BOTTOM "BOTTOM-AR_1V8 1" (solid, remove dead copper, pour order 1218): 462 vertices, not listed, extent 1980,956.11 2222,1554.5
AR_1P3_RF1 on BOTTOM "BOTTOM-AR_1P3_RF1" (solid, remove dead copper, pour order 1220): 109 vertices, not listed, extent 1709.24,1444.5 2686.52,1787.14
PMIC_1V0 on BOTTOM "GND 1-No Net" (solid, remove dead copper, pour order 1221): 36 vertices, not listed, extent 1198.58,621.88 1691.56,1866.4
MCU_5V on L3 "L3-MCU_5V" (solid, remove dead copper, pour order 1186): 17 vertices, not listed, extent 405,144.56 1866.22,592.98
GND on L3 "L3-GND 6" (solid, remove dead copper, pour order 1188): 722 vertices, not listed, extent -72.75,-132.5 3047.25,2372.5
AR_1V2 on L4 "L4-PMIC_1V2" (solid, remove dead copper, pour order 1189): 34 vertices, not listed, extent 1703.01,1411.5 2381.9,1819.48
5V_IN on L4 "L4-5V_IN" (solid, remove dead copper, pour order 1195): 471 vertices, not listed, extent 408.75,164.5 1597.98,2206.5
5V_UNREG on L4 "L4-5V_UNREG" (solid, remove dead copper, pour order 1193): 261 vertices, not listed, extent 1304.65,152.5 1795.2,1291.05
AR_1V8 on L4 "L4-AR_1V8" (solid, remove dead copper, pour order 1191): 509 vertices, not listed, extent 1942.47,848.07 2562,1589.5
GND on L4 "L4-GND" (solid, remove dead copper, pour order 1196): 722 vertices, not listed, extent -72.75,-132.5 3047.25,2372.5
GND on L2 "L2-GND 1" (solid, remove dead copper, pour order 1183): 2424.5,367 2424.5,120 2669.5,120 2669.5,367 2424.5,367
GND on L2 "L2-GND 2" (solid, remove dead copper, pour order 1184): 726 vertices, not listed, extent -72.74,-132.49 3047.24,2372.49
GND on L5 "L5-GND" (solid, remove dead copper, pour order 1197): 722 vertices, not listed, extent -72.75,-132.5 3047.25,2372.5

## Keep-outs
Keep-Out Layer:
  text ".Layer_Name" at -523,-1458.49 h60

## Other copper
TOP:
  text "1" at 76.39,102.36 h50
  text ".Layer_Name" at -523,-1458.49 h60
L2:
  text "2" at 68.06,102.36 h50
  text ".Layer_Name" at -523,-1458.49 h60
L3:
  text "3" at 68.06,102.36 h50
  text ".Layer_Name" at -523,-1458.49 h60
L4:
  text "4" at 68.06,102.36 h50
  text ".Layer_Name" at -523,-1458.49 h60
L5:
  text "5" at 68.06,102.36 h50
  text ".Layer_Name" at -523,-1458.49 h60
BOTTOM:
  text "6" at 101.39,102.36 h50
  text ".Layer_Name" at -523,-1458.49 h60

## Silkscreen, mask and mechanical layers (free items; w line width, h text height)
Top Overlay:
  circle w6: c894.62,627.38 r17.83
  circle w6: c485.18,628.05 r17.83
  circle w6: c688.62,628.38 r17.83
  circle w6: c-42.06,1837.57 r14.11
  circle w6: c1489.33,267.42 r14.11
  circle w6: c2007.63,386.64 r7.14
  text "HD_CONN" at 325,1793.5 h35 r90
  text "GND" at -48.33,1613 h35 r90
  text "1243/1443-EVM" at 648,1502.5 h30
  text "PROC010 REV B" at 652,1437.33 h30
  text "GPIO1" at 504.55,1382.74 h35 r90
  text "SPI" at 569.09,1196.05 h35 r90
  text "CAN" at 987.03,1180.35 h35 r90
  text "NRST" at 504.55,1144.97 h35 r90
  text "ON" at 914.7,1109.62 h35 r90.31
  text "SOP2" at 424,836.5 h35 r90
  text "SOP1" at 624,831.5 h35 r90
  text "SOP0" at 829,831.5 h35 r90
  text "5V" at 278.28,691.14 h35 r90
  text "NERR_OUT" at 107.44,686.5 h35 r90
  text "5V_IN" at 1117.5,271 h35
  text "NRST" at 298.71,228.51 h35 r90
  text "WARMRST" at 134.9,184 h32 r89.47
  text "GND" at 679.67,133 h35 r90
  text "CAN_L" at 963.67,65 h35 r90
  text "CAN_H" at 439.67,64 h35 r90
  text "USB" at 1958,-52.5 h35 r90
  text ".Layer_Name" at -523,-1458.49 h60
Bottom Overlay:
  drawing of 8192 lines, arcs and shapes, not listed
  text "GND" at 1635.34,2394.5 h35 r90
  text "GND" at 1736.34,2394.5 h35 r90
  text "GND" at 544.67,2389.5 h35 r90
  text "3V3" at 1842.66,2383.93 h30 r90
  text "GND" at 691.34,695.5 h35 r90
  text "GND" at 1639.34,609.5 h35 r90
  text "GND" at 1748.34,608.5 h35 r90
  text ".Layer_Name" at -523,-1458.49 h60
Top Paste:
  text ".Layer_Name" at -523,-1458.49 h60
Bottom Paste:
  text ".Layer_Name" at -523,-1458.49 h60
Top Solder:
  text ".Layer_Name" at -523,-1458.49 h60
  text ".Layer_Name" at -523,-1458.49 h60
Bottom Solder:
  text ".Layer_Name" at -523,-1458.49 h60
Drill Guide:
  text ".Layer_Name" at -523,-1458.49 h60
M1 Board Outline:
  the board outline again, w10
M3 3D STEP Top:
  drawing of 2189 lines, arcs and shapes, not listed
  text ".Layer_Name" at -523,-1458.49 h60
M4 3D STEP Bottom:
  drawing of 3547 lines, arcs and shapes, not listed
  text ".Layer_Name" at -523,-1458.49 h60
M5 Assembly Top:
  region: 1573.73,232.01 1541.58,232.01 1541.58,199 1573.73,199
  rectangle: 3.25,1755.12 61.5,1795.24
  rectangle: 392.36,652.17 425.79,686.46
  rectangle: 595.1,653.88 628.11,683.89
  rectangle: 804.71,651.74 836.86,684.75
  rectangle: 505.35,-45.85 561.85,-0.8
  lines w10: -1392,-1530.17 5208,-1530.17 ; -1392,-1326.83 5210,-1326.83 ; -1392,-1123.5 -1392,-1733.5 2613,-1733.5 5210,-1733.5 5210,-1123.5 -1391.5,-1123.5 -1391.5,-1733.5 184,-1733.5 ; 1073,-1733.5 1073,-1123.5 ; 2340,-1326.83 2340,-1123.5 ; 3180,-1326.83 3180,-1123.5 ; 3802,-1740 3802,-1537.17
  text "COMPONENTS MARKED 'DNP' SHOULD NOT BE POPULATED." at 53.5,-918.5 h60
  text "ASSEMBLY VARIANT:" at 53,-1034 h60
  text ".VariantName" at 1089,-1034 h60
  text "PCB VIEWED FROM TOP SIDE" at -1328.5,-1255.67 h60
  text "BOARD #:" at 1148,-1255.67 h60
  text ".PRJ_Number" at 1693.5,-1255.67 h60
  text "REV:" at 2538,-1255.67 h60
  text ".PCB_Rev" at 2829.5,-1255.67 h60
  text "SVN REV:" at 3376,-1255.67 h60
  text ".VersionControl_RevNumber" at 3882,-1255.67 h60
  text "TID #:" at 1148,-1459 h60
  text ".TID" at 1693.5,-1459 h60
  text "PLOT NAME =" at -1328.5,-1664.34 h60
  text ".plot_File_Name" at -523,-1664.34 h60
  text "GENERATED    :" at 1150,-1664.34 h60
  text ".Print_Date" at 2019.5,-1664.34 h60
  text ".Print_Time" at 2748.5,-1664.34 h60
  text "TEXAS INSTRUMENTS" at 4013,-1664.34 h60
M6 Assembly Bottom:
  rectangle: 477.5,309.5 520.87,346.52
  rectangle: 477.5,2009.5 520.08,2041.65
  lines w10: -1392.5,-1327.33 5209.5,-1327.33 ; -1390.5,-1530.67 5209.5,-1530.67 ; 15.5,-1740.5 15.5,-1537.67 ; 637.5,-1327.33 637.5,-1124 ; 1477.5,-1327.33 1477.5,-1124 ; 2744.5,-1734 2744.5,-1124 ; 3633.5,-1734 5209,-1734 5209,-1124 -1392.5,-1124 -1392.5,-1734 1204.5,-1734 5209.5,-1734 5209.5,-1124
  text "COMPONENTS MARKED 'DNP' SHOULD NOT BE POPULATED." at 5002,-918 h60
  text ".VariantName" at 3958,-1034 h60
  text "ASSEMBLY VARIANT:" at 4997,-1034 h60
  text ".VersionControl_RevNumber" at -64.5,-1256.17 h60
  text "SVN REV:" at 441.5,-1256.17 h60
  text ".PCB_Rev" at 988,-1256.17 h60
  text "REV:" at 1279.5,-1256.17 h60
  text ".PRJ_Number" at 2124,-1256.17 h60
  text "BOARD #:" at 2669.5,-1256.17 h60
  text "PCB VIEWED FROM BOTTOM SIDE" at 5146,-1256.17 h60
  text ".TID" at 2124,-1459.5 h60
  text "TID #:" at 2669.5,-1459.5 h60
  text "TEXAS INSTRUMENTS" at -195.5,-1664.84 h60
  text ".Print_Time" at 1069,-1664.84 h60
  text ".Print_Date" at 1798,-1664.84 h60
  text "GENERATED    :" at 2667.5,-1664.84 h60
  text ".plot_File_Name" at 4340.5,-1664.84 h60
  text "PLOT NAME =" at 5146,-1664.84 h60
1:
  lines w1: 2633.36,918.75 2633.36,1666.78 3042.41,1666.78 3042.41,918.75 2633.36,918.75
M9 Title Sheet:
  lines w1: -25,0 25,0 ; 0,-25 0,25
  lines w10: -1591.5,441.5 -1391.5,441.5 ; -1591.5,2816.5 -1391.5,2816.5 ; -1591.5,5191.5 -1391.5,5191.5 ; 908.5,-1933.5 908.5,-1733.5 ; 908.5,7366.5 908.5,7566.5 ; 3408.5,-1933.5 3408.5,-1733.5 ; 3408.5,7366.5 3408.5,7566.5 ; 5221,-1733.5 5221,-1123.5 10203.5,-1123.5 ; 5908.5,-1933.5 5908.5,-1733.5 ; 5908.5,7366.5 5908.5,7566.5 ; 8408.5,-1933.5 8408.5,-1733.5 ; 8408.5,7366.5 8408.5,7566.5 ; 10203.5,-1733.5 10203.5,-1123.5 ; 10203.5,-1423.5 13203.5,-1423.5 ; 10203.5,-823.5 13203.5,-823.5 ; 10204.5,-229.5 13204.5,-229.5 ; 10908.5,-1933.5 10908.5,-1733.5 ; 10908.5,7366.5 10908.5,7566.5 ; 11708.5,-1723.5 11708.5,-1123.5 ; 13203.5,-1123.5 10203.5,-1123.5 ; 13203.5,-523.5 10203.5,-523.5 ; 13208.5,-533.5 13208.5,-1733.5 ; 13208.5,271 10204.5,271 10203.5,271 10203.5,-229.5 10203.5,-523.5 ; 13208.5,441.5 13408.5,441.5 ; 13208.5,2816.5 13408.5,2816.5 ; 13208.5,5191.5 13408.5,5191.5 ; 10203.5,-1123.5 10203.5,-523.5 ; 13208.5,-1733.5 -1391.5,-1733.5 -1391.5,7366.5 13208.5,7366.5 13208.5,-1733.5 ; -1591.5,-1933.5 13408.5,-1933.5 13408.5,7566.5 -1591.5,7566.5 -1591.5,-1933.5
  text "1" at -360.16,7436.5 h70
  text "2" at 2135.5,7436.5 h70
  text "3" at 4624.84,7436.5 h70
  text "4" at 7131.51,7436.5 h70
  text "5" at 9630.5,7436.5 h70
  text "6" at 12135.5,7436.5 h70
  text "A" at -1516.5,6293.5 h70
  text "A" at 13283.5,6293.5 h70
  text "B" at -1516.5,3913.5 h70
  text "B" at 13283.5,3913.5 h70
  text "C" at -1516.5,1538.5 h70
  text "C" at 13283.5,1538.5 h70
  text "PROJECT TITLE:" at 10243.5,-322.5 h45
  text ".PRJ_Title" at 10293.5,-455.83 h70
  text "DESIGNED FOR:" at 10243.5,-623.5 h45
  text ".PRJ_Customer" at 10293.5,-763.5 h70
  text "D" at -1516.5,-831.5 h70
  text "D" at 13283.5,-831.5 h70
  text "FILE NAME:" at 10243.5,-923.5 h45
  text ".PCB_File_Name_No_Path" at 10293.5,-1043.5 h70
  text "Texas Instruments (TI) and/or its licensors do not warrant the accuracy or completeness of this specification" at 5274,-1205.34 h45
  text "ENGINEER:" at 10243.5,-1213.5 h45
  text "LAYOUT BY:" at 11748.5,-1213.5 h45
  text "or any information contained therein. TI and/or its licensors do not warrant that this design will meet" at 5229.01,-1318 h45
  text ".PRJ_Engineer" at 10293.5,-1368.49 h70
  text ".PCB_Layout" at 11799,-1368.49 h70
  text "the specifications, will be suitable for your application or fit for any particular purpose, or will operate in" at 5229.01,-1430.67 h45
  text "ALTIUM DESIGNER VERSION:" at 11748.5,-1523.5 h45
  text "an implementation. TI and/or its licensors do not warrant that the design is production worthy. You should" at 5229.01,-1543.33 h45
  text "completely validate and test your design implementation to confirm the system functionality for your application." at 5274,-1656 h45
  text ".print_Scale" at 10293.5,-1656.83 h70
  text ".Application_BuildNumber" at 11799,-1656.83 h70
  text "1" at -360.16,-1863.5 h70
  text "2" at 2135.5,-1863.5 h70
  text "3" at 4624.84,-1863.5 h70
  text "4" at 7131.51,-1863.5 h70
  text "5" at 9630.5,-1863.5 h70
  text "WO # : 307314-7312-D" at 12135.5,-1863.5 h70
M10 Fab Notes:
  drawing of 211 lines, arcs and shapes, not listed
  text "DESIGN INFORMATION" at 11282.02,5756.17 h60
  text "3.9" at 11684.18,5628.43 h60
  text "MIN. TRACK WIDTH:" at 10637.46,5624.05 h60
  text "MIL" at 11888.46,5624.05 h60
  text "3.9" at 11684.18,5505.31 h60
  text "MIN. CLEARANCE:" at 10637.46,5499.92 h60
  text "MIL" at 11887.46,5493.05 h60
  text "13.77" at 11607.21,5377.48 h60
  text "MIN. VIA PAD SIZE:" at 10637.46,5375.8 h60
  text "MIL" at 11888.46,5375.8 h60
  text "0.05mm (2MIL)" at 11332.46,5245.9 h60
  text "MINIMUM ANNULAR RING" at 10308.23,5237.67 h60
  text "EXTERNAL" at 12040.46,5237.67 h60
  text "PER" at 10508.23,5127.55 h60
  text "IPC-D-275 CLASS 2 LEVEL C" at 10728.23,5127.54 h60
  text "MIL, HOLES" at 12216.46,5027.07 h60
  text "+/-" at 11824,5018.48 h60
  text "+/-" at 12678,5018.48 h60
  text "REGISTRATION TOLERANCES:" at 10308.23,5017.42 h60
  text "METAL" at 11508,5017.42 h60
  text "2" at 12084.2,5017.42 h60
  text "3" at 12917.2,5017.42 h60
  text "MIL" at 13033.46,5017.42 h60
  text "HOLE SIZE TOLERANCE (UNLESS OTHERWISE SPECIFIED):" at 10308.23,4919.1 h60
  text "+/-" at 12678,4916.23 h60
  text "3" at 12917.2,4915.17 h60
  text "MIL" at 13033.46,4915.17 h60
  text "MATERIAL:" at 10233.46,4777.52 h60
  text "FR-4 High Tg" at 11219.9,4649 h60
  text "REFER STACKUP" at 12479.29,4645.02 h60
  text "X" at 11955.46,4641.01 h60
  text "FR-408" at 10654.46,4636.49 h60
  text "OTHER" at 12142.46,4636.49 h60
  text "X" at 12138.91,4493.91 h60
  text "62 MIL (1.6mm) +/-10%" at 10974.56,4493.46 h60
  text "57.14 MIL +/-10%" at 12537.59,4492.07 h50
  text "THICKNESS:" at 10308.23,4485.24 h60
  text "OTHER" at 12259.46,4485.24 h60
  text "TOLERANCE:" at 10308.23,4346.92 h60
  text "X" at 11156.46,4346.92 h60
  text "ANSI IPC-6012 TYPE 3 CLASS 2" at 11334.48,4346.92 h60
  text "OTHER +/-" at 11334.46,4202.73 h60
  text "BOW & TWIST:" at 10308.23,4057.54 h60
  text "X" at 11156.46,4057.54 h60
  text "ANSI IPC-6012 TYPE 3 CLASS 2" at 11334.48,4057.54 h60
  text "OTHER +/-" at 11334.46,3910.85 h60
  text "DRILLING:" at 10233.46,3780.23 h60
  text "NC_DRILL FILES" at 11994.46,3675.04 h60
  text "REFERENCE:" at 10308.23,3671.1 h60
  text "X" at 10965.46,3671.01 h60
  text "AS SHOWN" at 11143.46,3671.1 h60
  text "X" at 11866.46,3671.1 h60
  text "OTHER" at 12292.46,3528.85 h60
  text "PTH COPPER THICKNESS:" at 10307.91,3525.32 h60
  text "X" at 11447.14,3525.32 h60
  text "20-30 um" at 11575.14,3525.32 h60
  text "BOARD FINISH:" at 10233.46,3377.73 h60
  text "SILKSCREEN:" at 10388.68,3267.6 h60
  text "X" at 11346.46,3267.6 h60
  text "TOP" at 11463.46,3267.6 h60
  text "X" at 11856.46,3267.6 h60
  text "BOTTOM" at 11974.46,3267.6 h60
  text "SILKSCREEN COLOR:" at 10388.68,3112.41 h60
  text "X" at 11345.46,3112.41 h60
  text "WHITE" at 11463.46,3112.41 h60
  text "OTHER" at 11974.46,3112.41 h60
  text "REFER NOTE 8" at 12531.96,2973.55 h60
  text "GREEN" at 11594.46,2968.96 h60
  text "X" at 12068.46,2968.96 h60
  text "OTHER" at 12212.46,2968.96 h60
  text "SOLDER RESIST COLOR:" at 10388.68,2962.1 h60
  text "X" at 11476.46,2814.71 h60
  text "MATTE" at 11594.46,2814.71 h60
  text "SEMI-GLOSS" at 12212,2814.07 h60
  text "IMMERSION GOLD (ENIG)" at 11294.46,2641.94 h60
  text "ENEPIG" at 12632,2634.72 h60
  text "SURFACE FINISH:" at 10233.46,2633.72 h60
  text "REFER NOTE 7" at 12356.19,2502.8 h60
  text "IMM. TIN/SILVER OR EQUIV" at 10563,2496.4 h60
  text "X" at 11822.92,2493.72 h60
  text "OTHER" at 11994.46,2492.47 h60
  text "ARRAY/PANEL:" at 10233.46,2337.09 h60
  text "CUT AND TRIM PER M1 BOARD OUTLINE" at 11294.46,2328.87 h60
  text "NOTES : UNLESS OTHERWISE SPECIFIED." at 4571.25,2263.62 h60
  text "N.C. ROUTE" at 11294.46,2192.9 h60
  text "X" at 11982.46,2192.9 h60
  text "V. SCORE" at 12160.46,2192.9 h60
  text "1. ALL VIAS ARE TENTED ON BOTH SIDES UNLESS SOLDERMASK OPENED IN GERBER." at 4680.97,2112.73 h60
  text "CERTIFICATION:" at 10233.46,2063.77 h60
  text "MATERIALS AND WORKMANSHIP FOR ALL PCBS" at 10958.46,2063.77 h60
  text "2. ALL VIAS ON PAD INCLUDING BGA AREA SHOULD BE FILLED WITH NON CONDUCTIVE EPOXY AND SURFACE SHOULD BE FLAT" at 4668.66,1987.45 h60
  text "TO MEET OR EXCEED THE REQUIREMENTS OF:" at 10958.46,1969.71 h60
  text "THERE ARE MANY VIAS ON THE PCB WHICH ARE EITHER ON THE PADS OR CLOSE TO PADS" at 4787.44,1880.17 h60
  text "X" at 10595.97,1841.08 h60
  text "ANSI IPC-A-600F CLASS ->" at 10723.96,1841.08 h60
  text "X" at 12371.97,1841.08 h60
  text "2" at 12481.96,1841.08 h60
  text "1" at 12166.96,1839.58 h60
  text "3" at 12835.96,1839.58 h60
  text "THESE NEED TO BE FILLED WITH A NON-CONDUCTIVE EPOXY TO ENSURE FLAT SURFACE." at 4787.44,1779.43 h60
  text "X" at 11407.97,1693.39 h60
  text "RoHS" at 11535.96,1693.39 h60
  text "OTHER" at 12180.36,1693.39 h60
  text "PER ORDER" at 12577.42,1693.39 h60
  text "BGA AREA VIAS SHOULD BE CAPPED WITH COPPER PLATING TO ENSURE FLAT SURFACE" at 4792.93,1677.9 h60
  text "FLATNESS TOLERANCE FOR VIA ON PADS: +0.000 /- 0.001 INCHES ON BOTH SIDES." at 4792.93,1569.81 h60
  text "ALL BOARDS MUST MEET OR EXCEED UL94-V0 REQUIREMENTS." at 10261,1539.57 h60
  text "3. MANUFACTURER'S IDENTIFICATION, DATECODE LETTER SHALL BE SILKSCREENED ON SOLDER SIDE OF THE BOARD." at 4669.6,1436.68 h60
  text "PCB MUST BEAR THE UL94V-0 UL REGISTERED MATERIAL ID NUMBER" at 10261,1423.5 h60
  text "4. TRACE WIDTH SHOULD BE ACCURATELY ETCHED. MAX TOLERANCE +/- 1 MIL" at 4669.6,1299.99 h60
  text "ADDITIONAL REQUIREMENTS:" at 10233.46,1254.08 h60
  text "5. FOR IMPEDANCE DETAILS REFER STACKUP & IMPEDANCE TABLE." at 4669.6,1159.9 h60
  text "MICROSECTION:" at 10308.23,1146.95 h60
  text "YES" at 11213.96,1146.95 h60
  text "REQUIRED" at 12075.46,1002.62 h60
  text "BARE BOARD ELEC. TEST:" at 10308.23,999.76 h60
  text "NONE" at 11613.96,999.76 h60
  text "X" at 11957.46,999.76 h60
  text "PER ORDER" at 12667.46,999.76 h60
  text "6. SOLDER MASK OPENING IS KEPT SAME SIZE AS PAD (1:1) FOR ALL COMPONENTS EXCEPT U2" at 4669.6,995.9 h60
  text "THE MANUFACTURER IS REQUESTED TO SIZE IT AS PER THEIR SOLDERMASK TOLERANCE." at 4784.01,889.17 h60
  text "XX MIL VIAS REQUIRE NON-CONDUCTIVE FILL AND PLANARIZE" at 10476.38,794.82 h59
  text "FOR U2 (BGA) PLEASE FOLLOW SAME SOLDERMASK SIZE AS GERBER" at 4796.11,779.23 h60
  text "XX MIL VIAS REQUIRE CONDUCTIVE FILL AND PLANARIZE" at 10484.38,690.84 h60
  text "7. SURFACE FINISH: IMMERSION SILVER" at 4669.6,641.3 h60
  text "OUTER XX MIL TRACES REQUIRE 50 OHM SINGLE-ENDED IMPEDANCE" at 10483.39,527.46 h56
  text "8. SOLDERMASK ON BOTH SIDES OF THE BOARD SHALL BE LPI, COLOR RED." at 4669.6,467.34 h60
  text "LAYER 2 & 3 (INNER LAYERS) XX MIL WIDE, XX MIL SPACE / TRACES REQUIRE 100 OHM DIFFERENTIAL IMPEDANCE" at 10475.39,291.74 h60
  text "9. FOR ANTENNA ETCHING TOLERANCE REFER \"ANTENNA ETCHING REQUIREMETS\" DOCUMENT." at 4669.6,288.48 h60
  text "10. THE FOUR GND NET ANTENNAS NEAR Y1 ARE INTENTIONAL" at 4634.42,154.85 h60
M11 Gerber Information:
  lines w10: -1392,-1530.17 5208,-1530.17 ; -1392,-1326.83 5210,-1326.83 ; -1392,-1123.5 -1392,-1733.5 2613,-1733.5 5210,-1733.5 5210,-1123.5 -1391.5,-1123.5 -1391.5,-1733.5 184,-1733.5 ; 1073,-1733.5 1073,-1123.5 ; 2340,-1326.83 2340,-1123.5 ; 3180,-1326.83 3180,-1123.5 ; 3802,-1740 3802,-1537.17
  text "ALL ARTWORK VIEWED FROM TOP SIDE" at -1328.5,-1255.67 h60
  text "BOARD #:" at 1148,-1255.67 h60
  text ".PRJ_Number" at 1693.5,-1255.67 h60
  text "REV:" at 2538,-1255.67 h60
  text ".PCB_Rev" at 2829.5,-1255.67 h60
  text "SVN REV:" at 3376,-1255.67 h60
  text ".VersionControl_RevNumber" at 3882,-1255.67 h60
  text "LAYER NAME =" at -1328.5,-1458.49 h60
  text "TID #:" at 1148,-1459 h60
  text ".TID" at 1693.5,-1459 h60
  text "GENERATED    :" at 1150,-1664.34 h60
  text ".Print_Date" at 2019.5,-1664.34 h60
  text ".Print_Time" at 2748.5,-1664.34 h60
  text "TEXAS INSTRUMENTS" at 4013,-1664.34 h60
M12 Stackup:
  drawing of 480 lines, arcs and shapes, not listed
  text "LAYER STACKUP :" at -787.01,7220.54 h60
  text "Layer" at -787.72,7069.91 h50
  text "Name" at -444.79,7069.91 h50
  text "Material" at 331.33,7069.91 h50
  text "Thickness" at 1049.14,7069.91 h50
  text "Constant" at 1592,7069.91 h50
  text "Board Layer Stack" at 2068.22,7069.91 h50
  text "1" at -787.72,6969.91 h50
  text "Top Overlay" at -444.79,6969.91 h50
  text "2" at -787.72,6869.91 h50
  text "Top Solder" at -444.79,6869.91 h50
  text "Solder Resist" at 331.33,6869.91 h50
  text "0.80mil" at 1049.14,6869.91 h50
  text "3.5" at 1592,6869.91 h50
  text "3" at -787.72,6769.91 h50
  text "TOP" at -444.79,6769.91 h50
  text "Copper" at 331.33,6769.91 h50
  text "1.60mil" at 1049.14,6769.91 h50
  text "5" at -940.77,6764.82 h60
  text "4" at -787.72,6669.91 h50
  text "Dielectric 1" at -444.79,6669.91 h50
  text "RO4835 LOPRO" at 331.33,6669.91 h50
  text "4.00mil" at 1049.14,6669.91 h50
  text "3.66" at 1592,6669.91 h50
  text "5" at -787.72,6569.91 h50
  text "L2" at -444.79,6569.91 h50
  text "Copper" at 331.33,6569.91 h50
  text "1.20mil" at 1049.14,6569.91 h50
  text "IMPEDANCE TABLE :" at 3600.83,6555.94 h70
  text "L1-L2" at -1106.13,6551.81 h60 r90
  text "5" at 3430.22,6544.62 h70
  text "6" at -787.72,6469.91 h50
  text "Dielectric2" at -444.79,6469.91 h50
  text "FR4 370HR" at 331.33,6469.91 h50
  text "2.85mil" at 1049.14,6469.91 h50
  text "3.9" at 1592,6469.91 h50
  text "7" at -787.72,6369.91 h50
  text "Dielectric 3" at -444.79,6369.91 h50
  text "FR4 370HR" at 331.33,6369.91 h50
  text "2.85mil" at 1049.14,6369.91 h50
  text "3.9" at 1592,6369.91 h50
  text "8" at -787.72,6269.91 h50
  text "L3" at -444.79,6269.91 h50
  text "Copper" at 331.33,6269.91 h50
  text "1.20mil" at 1049.14,6269.91 h50
  text "LAYER NO" at 3653.01,6214.39 h70
  text "CONDUCTOR WIDTH" at 4298.52,6214.39 h70
  text "IMPEDANCE +/-10%" at 6498.49,6214.26 h70
  text "REFERENCE GND" at 7679.53,6214.26 h70
  text "9" at -787.72,6169.91 h50
  text "Dielectric4" at -444.79,6169.91 h50
  text "FR4 370HR" at 331.33,6169.91 h50
  text "28.00mil" at 1049.14,6169.91 h50
  text "4.36" at 1592,6169.91 h50
  text "DIFF. / PAIR / SPACING" at 5360.47,6154.24 h70
  text "CPWG / SPACING" at 5898.82,6148.65 h70
  text "10" at -787.72,6069.91 h50
  text "L4" at -444.79,6069.91 h50
  text "Copper" at 331.33,6069.91 h50
  text "1.20mil" at 1049.14,6069.91 h50
  text "L1-L6" at -1287.73,6062.58 h60 r90
  text "11" at -787.72,5969.91 h50
  text "Dielectric5" at -444.79,5969.91 h50
  text "FR4 370HR" at 331.33,5969.91 h50
  text "2.92mil" at 1049.14,5969.91 h50
  text "3.9" at 1592,5969.91 h50
  text "7.08mil" at 4585.89,5945.53 h70
  text "1 (TOP)" at 3762.55,5943.06 h70
  text "GND" at 7928.75,5942.93 h70
  text "6.73mil" at 5934.76,5942.19 h70
  text "N/A" at 5444.9,5939.72 h70
  text "50ohm" at 6746,5939.67 h70
  text "12" at -787.72,5869.91 h50
  text "Dielectric 6" at -444.79,5869.91 h50
  text "FR4 370HR" at 331.33,5869.91 h50
  text "2.92mil" at 1049.14,5869.91 h50
  text "3.9" at 1592,5869.91 h50
  text "13" at -787.72,5769.91 h50
  text "L5" at -444.79,5769.91 h50
  text "Copper" at 331.33,5769.91 h50
  text "1.20mil" at 1049.14,5769.91 h50
  text "14" at -787.72,5669.91 h50
  text "Dielectric7" at -444.79,5669.91 h50
  text "FR4 370HR" at 331.33,5669.91 h50
  text "4.00mil" at 1049.14,5669.91 h50
  text "4.26" at 1592,5669.91 h50
  text "5.2mil" at 4585.89,5650.53 h70
  text "1 (TOP)" at 3762.55,5648.06 h70
  text "GND" at 7928.75,5647.93 h70
  text "5mil" at 5444.9,5644.72 h70
  text "N/A" at 5979.8,5644.59 h70
  text "100ohm" at 6746,5644.67 h70
  text "15" at -787.72,5569.91 h50
  text "BOTTOM" at -444.79,5569.91 h50
  text "Copper" at 331.33,5569.91 h50
  text "1.60mil" at 1049.14,5569.91 h50
  text "16" at -787.72,5469.91 h50
  text "Bottom Solder" at -444.79,5469.91 h50
  text "Solder Resist" at 331.33,5469.91 h50
  text "0.80mil" at 1049.14,5469.91 h50
  text "3.5" at 1592,5469.91 h50
  text "17" at -787.72,5369.91 h50
  text "Bottom Overlay" at -444.79,5369.91 h50
  text "THIS IS AN IMPEDANCE CONTROLLED BOARD." at -138.1,5200.05 h75
  text "NOTE :" at -1292.53,5078.05 h75
  text "EXTERNAL LAYER CU THICKNESSES ARE FINISHED THICKNESS AFTER PLATING." at -1218.64,4910.1 h75
M13 Component Bodies Top:
  text ".Layer_Name" at -523,-1458.49 h60
M14 Component Bodies Bottom:
  text ".Layer_Name" at -523,-1458.49 h60
M15 Courtyards Top:
  text ".Layer_Name" at -523,-1458.49 h60
M16 Courtyards Bottom:
  text ".Layer_Name" at -523,-1458.49 h60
